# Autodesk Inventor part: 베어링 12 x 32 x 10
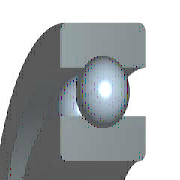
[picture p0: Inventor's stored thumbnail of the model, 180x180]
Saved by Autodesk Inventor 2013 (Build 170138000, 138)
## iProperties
IsCustomPart: 1
Created: 2012-02
Part Number: 베어링 12 x 32 x 10
Material: 강철, 연강
Description: 깊은 그루브 볼 베어링
Document SubType Name: Modeling
Standard: KS B 2023
Designer: test
Standards Organization: KS
Language: ko-KR
Size Designation: 6201 - 12 x 32 x 10
Categories: <MemberInstance><Categories><Category DisplayName="샤프트 부품" InternalName="7f7aeb1f-a693-4053-b835-cee3144e0d98" Mnemonic="SHFT"><Category DisplayName="베어링" Inter
Density: 1 g/cm^3
Author: test
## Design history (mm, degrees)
sketch "스케치" dims "d0" = 5.2 (= -0.26 x WD + 0.26 x BD)
  geometry: L1 (2.4, 11)-(7.6, 11); L2 (5, 11)-(5, 8.4); L3 (5, 11)-(5, 13.6); L4 (3.068, 9.26)-(0, 9.26); L5 (0, 6)-(10, 6); L6 (3.068, 12.74)-(0, 12.74); L7 (0, 16)-(10, 16); L8 (10, 6)-(10, 9.26); L9 (6.932, 9.26)-(10, 9.26); L10 (6.932, 12.74)-(10, 12.74); L11 (10, 16)-(10, 12.74); L12 (-1.4, 0)-(8.4, 0) reference; L13 (0, -0.3)-(0, 5.3) reference
  constraints: 22 end point, 4 point on line, 2 collinear, 2 perpendicular, 2 symmetric about line, 1 midpoint, 1 parallel, 14 other
  dimensions: "d9" = 12 diameter of L5 L12 (= WD); "d11" = 32 diameter of L7 L12 (= BD); "d12" = 10 distance between parallel lines of L8 L13 (= KB); "d13" = 18.52 diameter of L9 L12 (= 0.326 x BD + 0.674 x WD)
revolve "본체" stored, may be unused: angle "d6" = 90 deg
revolve "볼" stored, may be unused: angle "d7" = 90 deg
pattern_circular "IDS_ARRAYBALL[SIMPL:T]" dims angle "d3" = 360 deg
body "Solid1"
fillet "모깎기1" dims "d1" = 0.6 (= KRS)
other parameters: "WD" = 12 [user parameter; used in 5 equation terms], "BD" = 32 [user parameter; used in 5 equation terms], "KB" = 10 [user parameter; used in 1 equation term], "KRS" = 0.6 [user parameter; used in 1 equation term], "d4" = 0, "d5" = 0, "d8" = 0, "d14" = 0, "d15" = 0, "BBA" = 0 [user parameter], "BC0" = 3100000 [user parameter], "BC" = 6890000 [user parameter], "BR" = 16 (= 0.5 x BD) [user parameter], "WR" = 6 (= 0.5 x WD) [user parameter]
